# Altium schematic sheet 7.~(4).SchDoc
size 609 x 444 mm
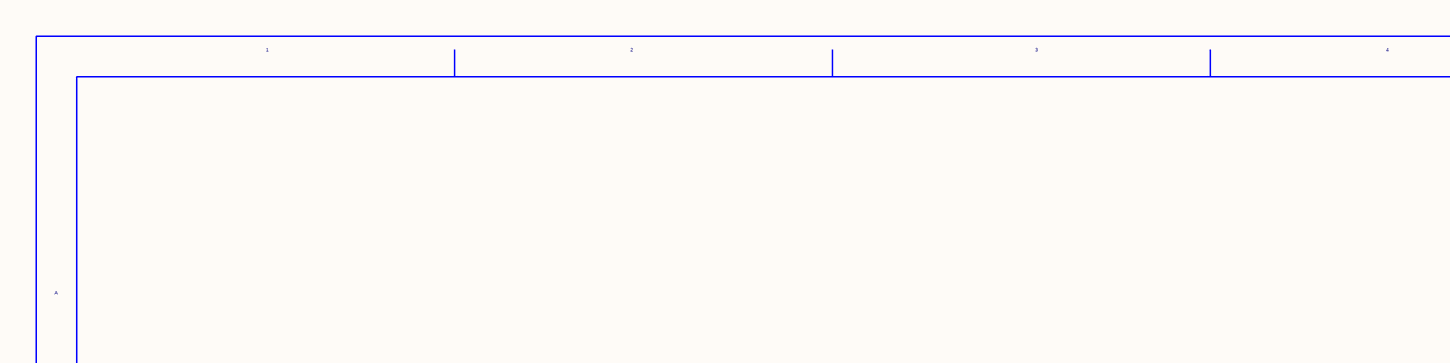
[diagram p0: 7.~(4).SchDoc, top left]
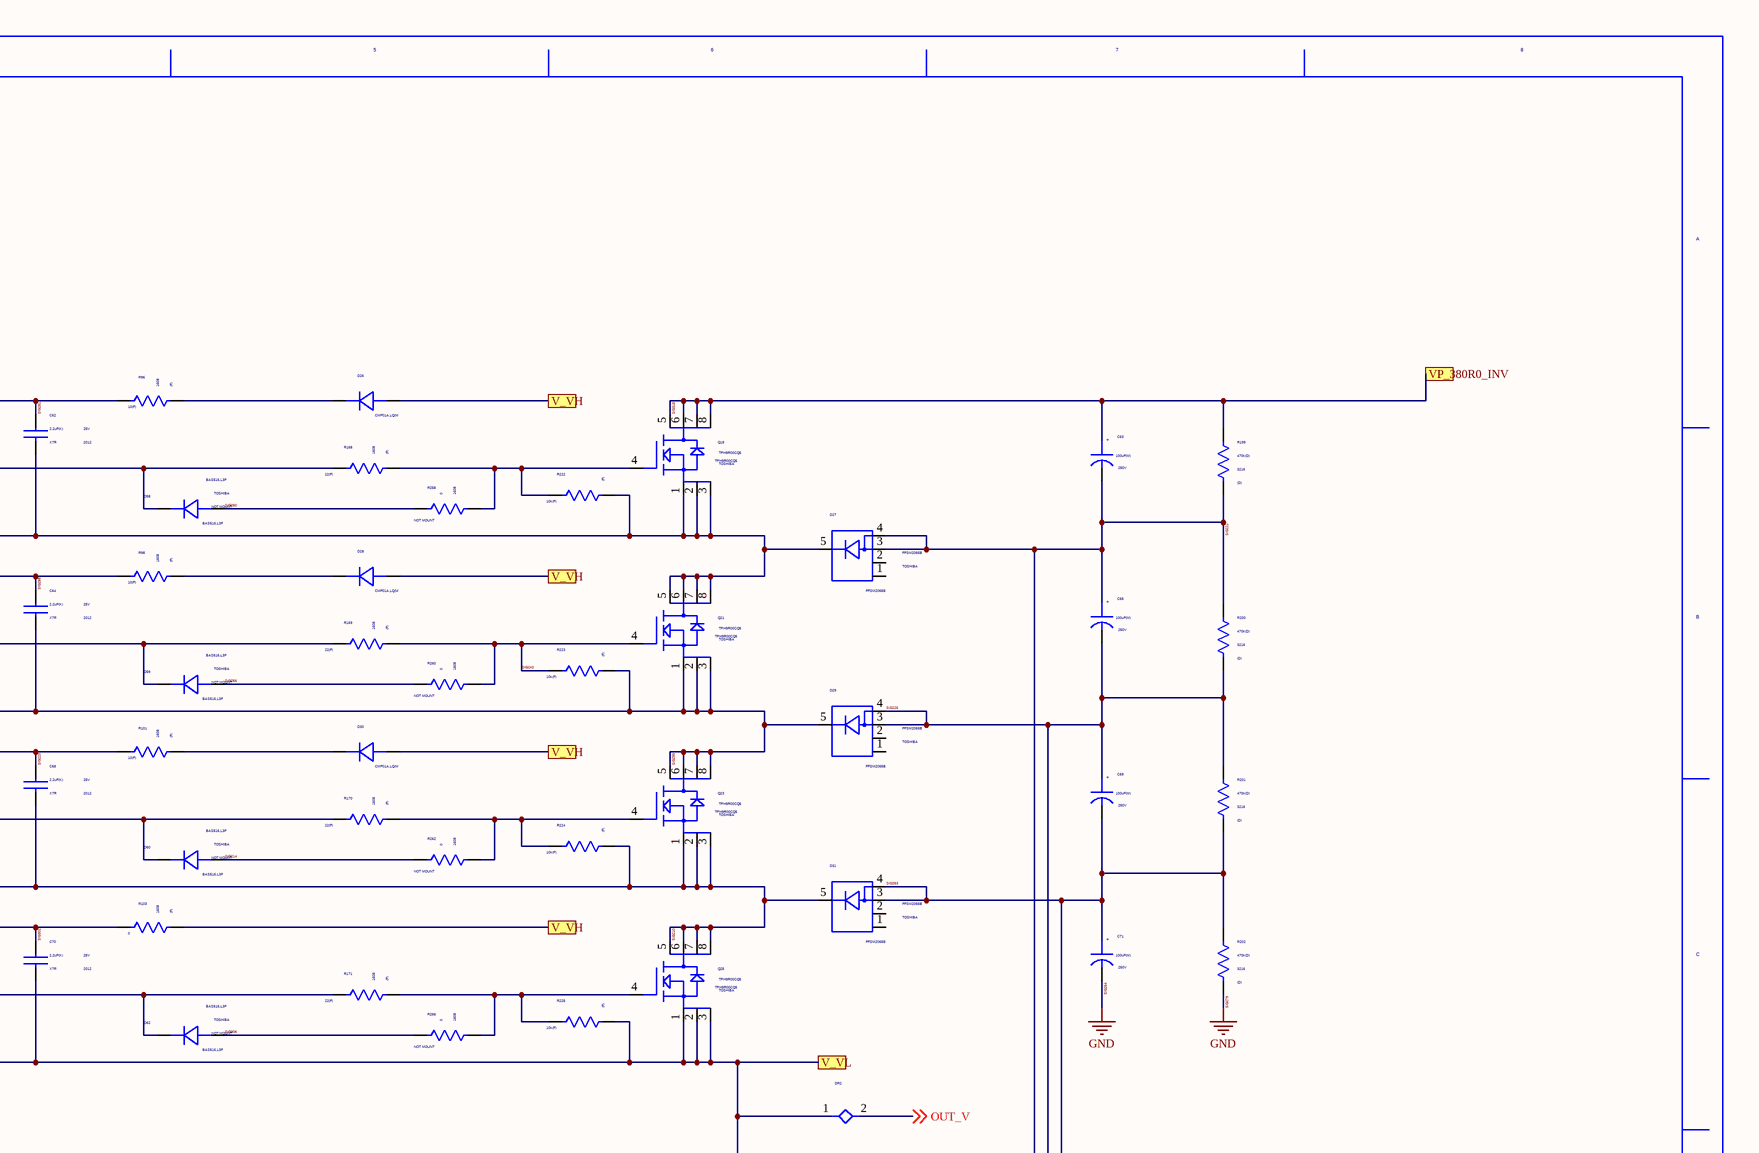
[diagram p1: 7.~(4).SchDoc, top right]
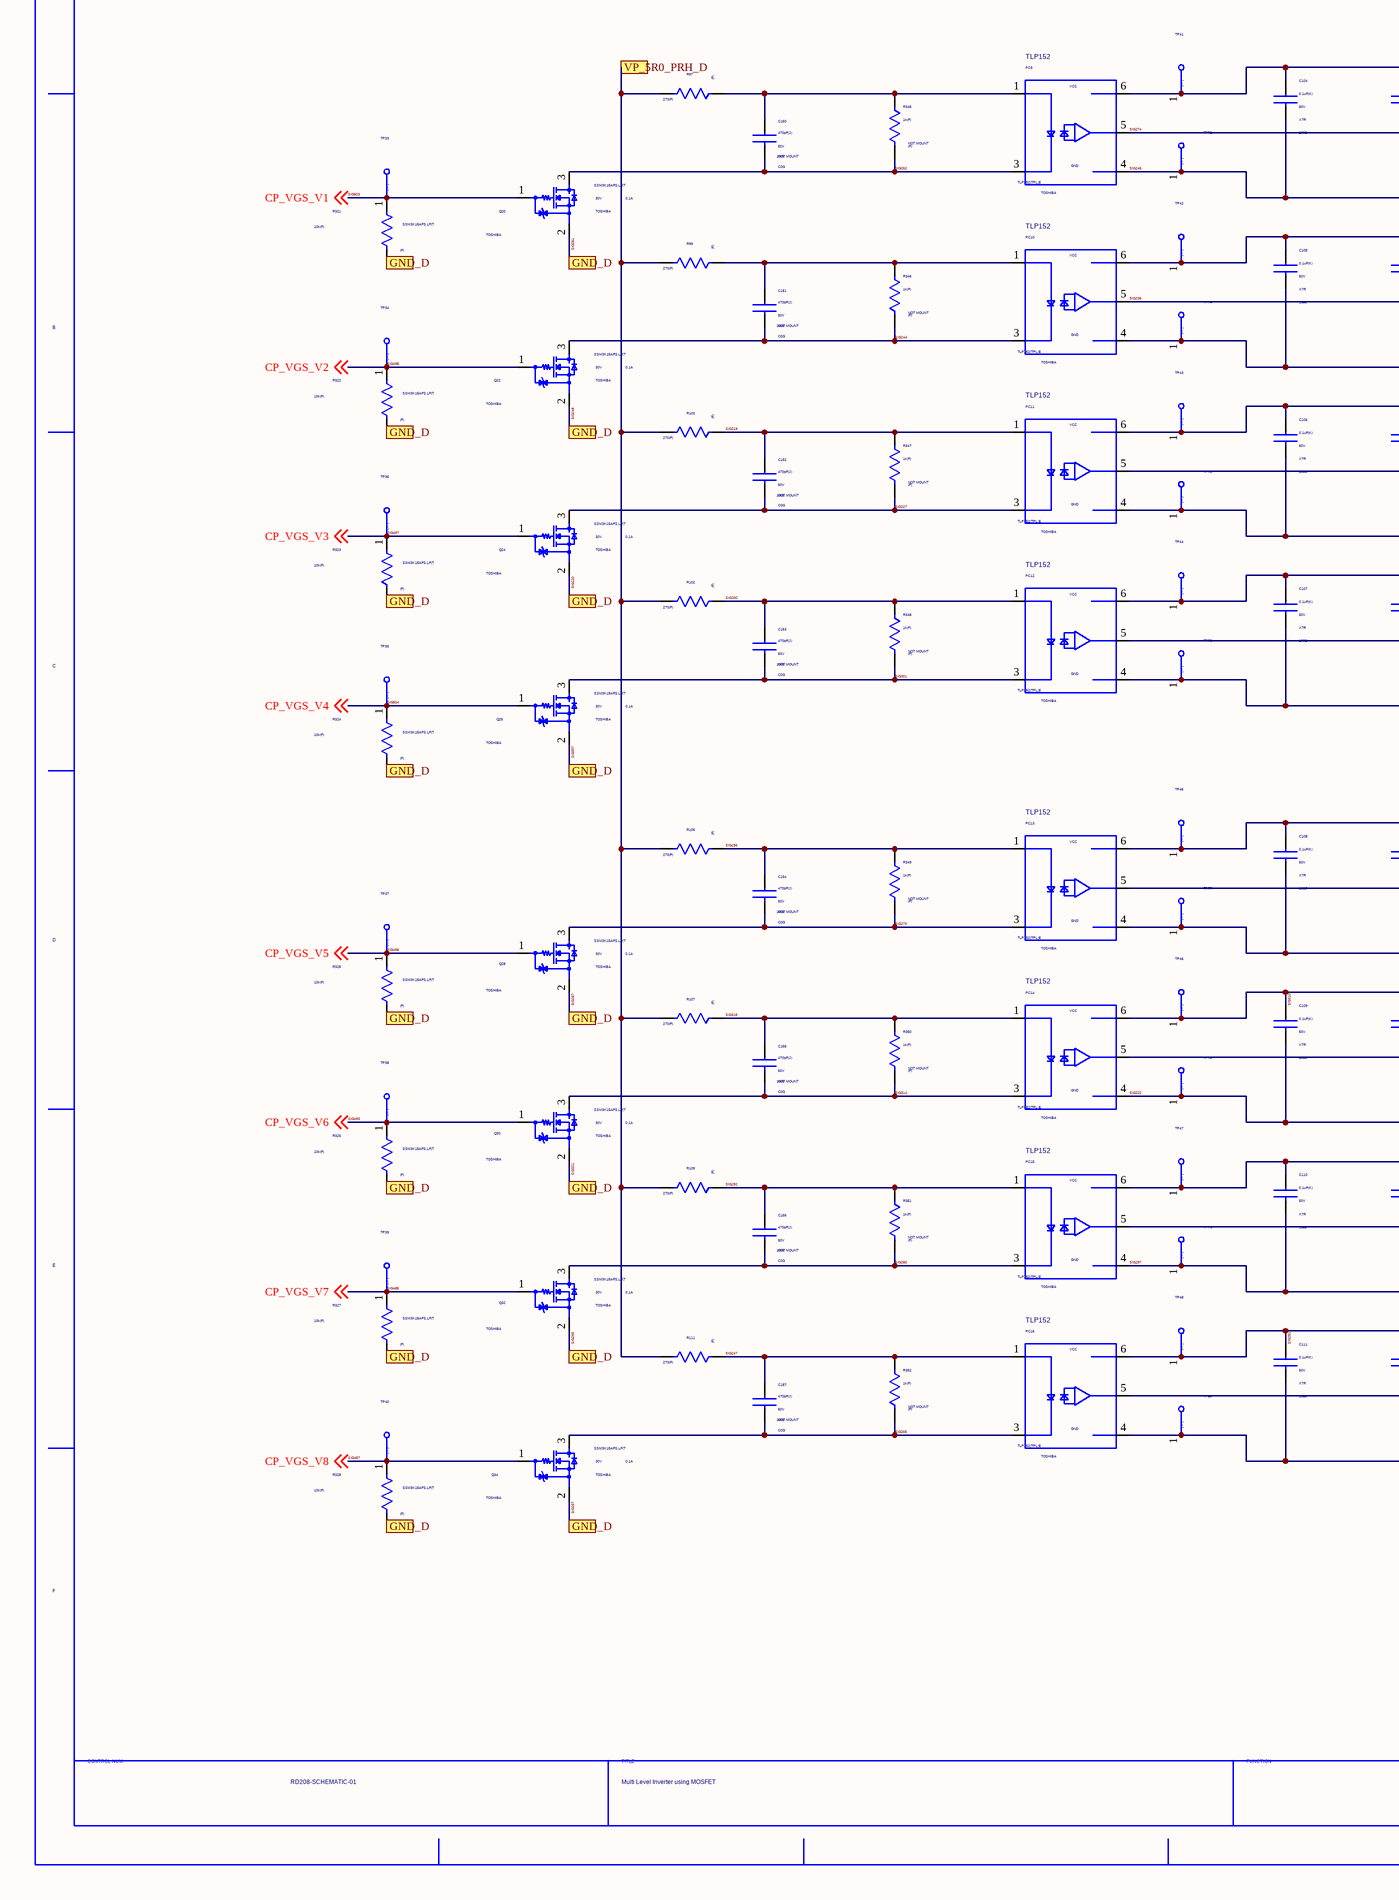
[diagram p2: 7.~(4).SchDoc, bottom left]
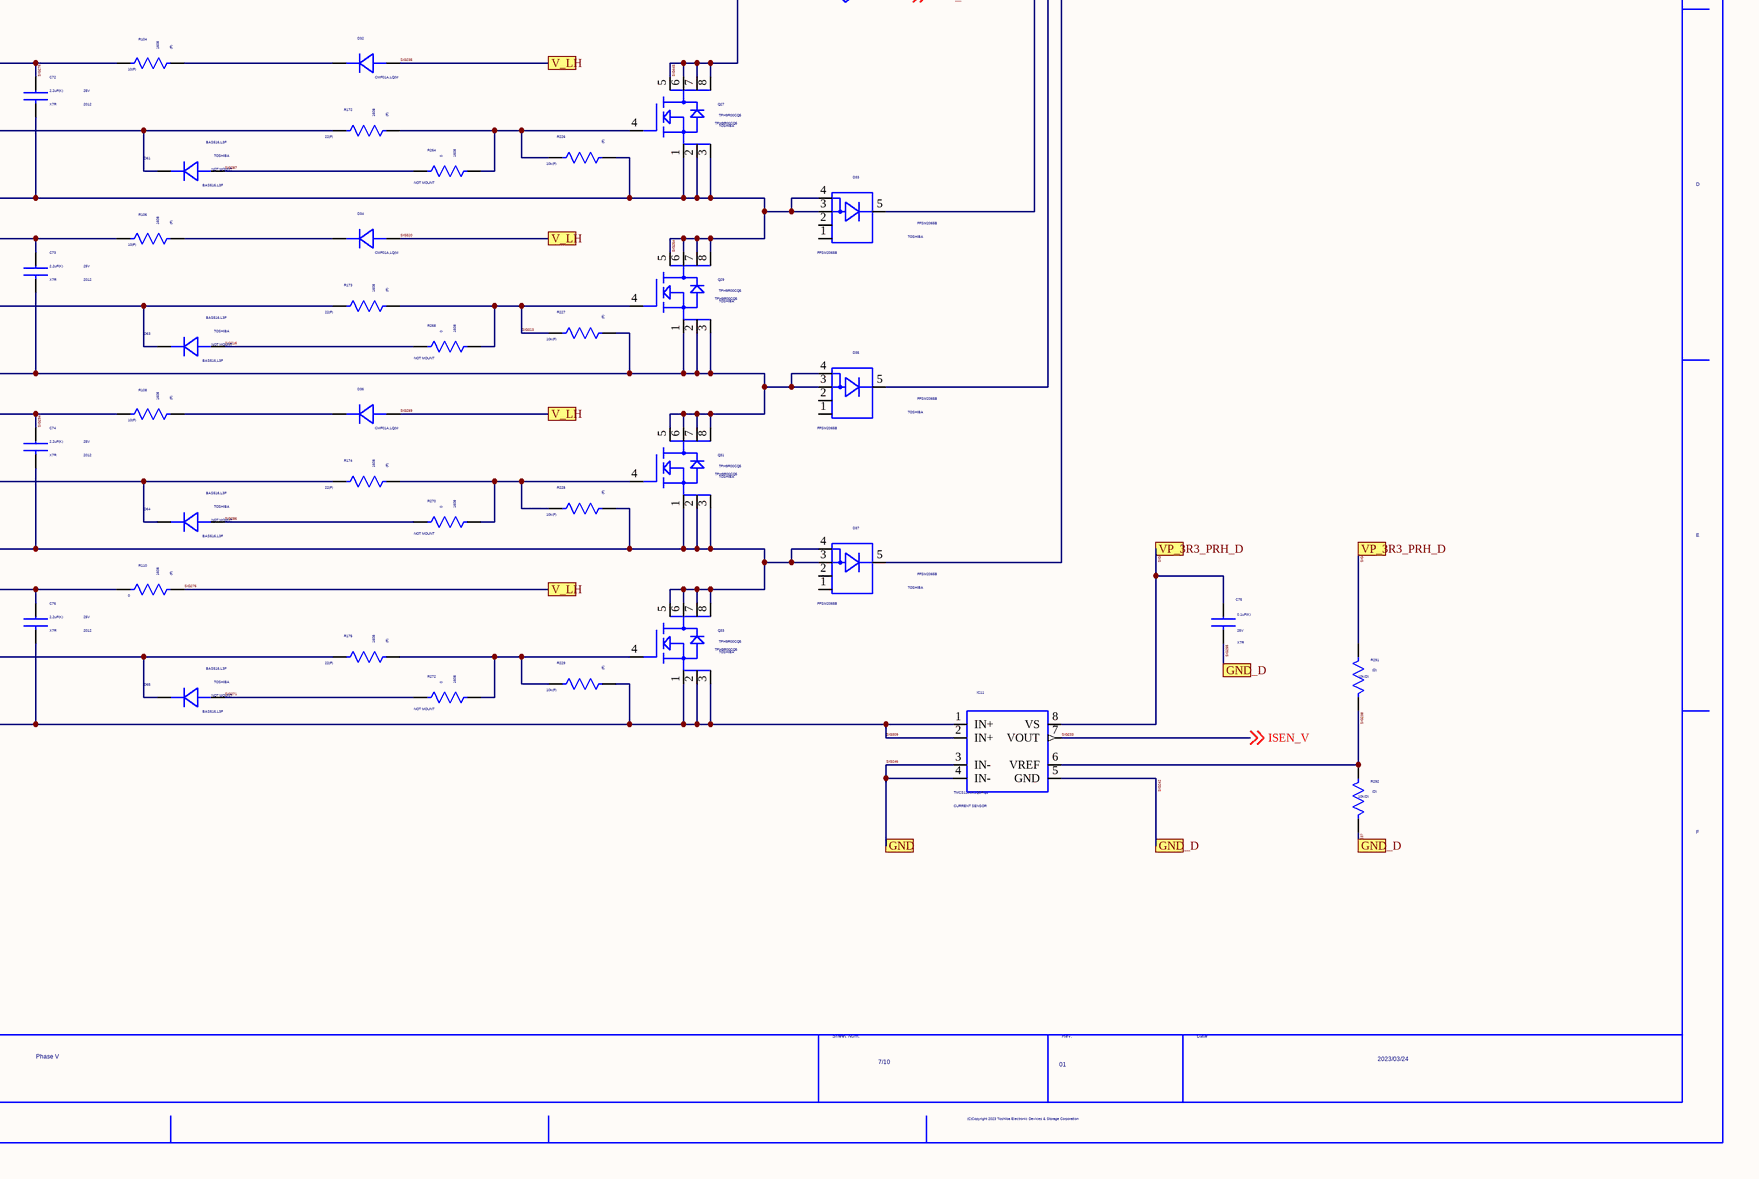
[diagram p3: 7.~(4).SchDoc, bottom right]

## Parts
C62  VAL2: 25V  SIZECODESMD: 2012  VALUE4: X7R  VAL1: 2.2uF(K)  (hidden comment: GRM21BR71E225KE11L)
C63  VAL2: 250V  VAL1: 100uF(M)  (hidden comment: EKMQ251ELL101ML25S)
C64  VAL2: 25V  SIZECODESMD: 2012  VALUE4: X7R  VAL1: 2.2uF(K)  (hidden comment: GRM21BR71E225KE11L)
C65  VAL2: 250V  VAL1: 100uF(M)  (hidden comment: EKMQ251ELL101ML25S)
C68  VAL2: 25V  SIZECODESMD: 2012  VALUE4: X7R  VAL1: 2.2uF(K)  (hidden comment: GRM21BR71E225KE11L)
C69  VAL2: 250V  VAL1: 100uF(M)  (hidden comment: EKMQ251ELL101ML25S)
C70  VAL2: 25V  SIZECODESMD: 2012  VALUE4: X7R  VAL1: 2.2uF(K)  (hidden comment: GRM21BR71E225KE11L)
C71  VAL2: 250V  VAL1: 100uF(M)  (hidden comment: EKMQ251ELL101ML25S)
C72  VAL2: 25V  SIZECODESMD: 2012  VALUE4: X7R  VAL1: 2.2uF(K)  (hidden comment: GRM21BR71E225KE11L)
C73  VAL2: 25V  SIZECODESMD: 2012  VALUE4: X7R  VAL1: 2.2uF(K)  (hidden comment: GRM21BR71E225KE11L)
C74  VAL2: 25V  SIZECODESMD: 2012  VALUE4: X7R  VAL1: 2.2uF(K)  (hidden comment: GRM21BR71E225KE11L)
C75  VAL2: 25V  VALUE4: X7R  VAL1: 0.1uF(K)  (hidden comment: GRM155R71E104KE14D)
C76  VAL2: 25V  SIZECODESMD: 2012  VALUE4: X7R  VAL1: 2.2uF(K)  (hidden comment: GRM21BR71E225KE11L)
C104  VAL2: 50V  SIZECODESMD: 1608  VALUE4: X7R  VAL1: 0.1uF(K)  (hidden comment: C1608X7R1H104K080AA)
C105  VAL2: 50V  SIZECODESMD: 1608  VALUE4: X7R  VAL1: 0.1uF(K)  (hidden comment: C1608X7R1H104K080AA)
C106  VAL2: 50V  SIZECODESMD: 1608  VALUE4: X7R  VAL1: 0.1uF(K)  (hidden comment: C1608X7R1H104K080AA)
C107  VAL2: 50V  SIZECODESMD: 1608  VALUE4: X7R  VAL1: 0.1uF(K)  (hidden comment: C1608X7R1H104K080AA)
C108  VAL2: 50V  SIZECODESMD: 1608  VALUE4: X7R  VAL1: 0.1uF(K)  (hidden comment: C1608X7R1H104K080AA)
C109  VAL2: 50V  SIZECODESMD: 1608  VALUE4: X7R  VAL1: 0.1uF(K)  (hidden comment: C1608X7R1H104K080AA)
C110  VAL2: 50V  SIZECODESMD: 1608  VALUE4: X7R  VAL1: 0.1uF(K)  (hidden comment: C1608X7R1H104K080AA)
C111  VAL2: 50V  SIZECODESMD: 1608  VALUE4: X7R  VAL1: 0.1uF(K)  (hidden comment: C1608X7R1H104K080AA)
C150  VAL2: 50V  SIZECODESMD: 1005  VALUE4: C0G  VAL1: 470pF(J)  NOTMOUNT: NOT MOUNT  (hidden comment: GRM1555C1H471JA01J)
C151  VAL2: 50V  SIZECODESMD: 1005  VALUE4: C0G  VAL1: 470pF(J)  NOTMOUNT: NOT MOUNT  (hidden comment: GRM1555C1H471JA01J)
C152  VAL2: 50V  SIZECODESMD: 1005  VALUE4: C0G  VAL1: 470pF(J)  NOTMOUNT: NOT MOUNT  (hidden comment: GRM1555C1H471JA01J)
C153  VAL2: 50V  SIZECODESMD: 1005  VALUE4: C0G  VAL1: 470pF(J)  NOTMOUNT: NOT MOUNT  (hidden comment: GRM1555C1H471JA01J)
C154  VAL2: 50V  SIZECODESMD: 1005  VALUE4: C0G  VAL1: 470pF(J)  NOTMOUNT: NOT MOUNT  (hidden comment: GRM1555C1H471JA01J)
C155  VAL2: 50V  SIZECODESMD: 1005  VALUE4: C0G  VAL1: 470pF(J)  NOTMOUNT: NOT MOUNT  (hidden comment: GRM1555C1H471JA01J)
C156  VAL2: 50V  SIZECODESMD: 1005  VALUE4: C0G  VAL1: 470pF(J)  NOTMOUNT: NOT MOUNT  (hidden comment: GRM1555C1H471JA01J)
C157  VAL2: 50V  SIZECODESMD: 1005  VALUE4: C0G  VAL1: 470pF(J)  NOTMOUNT: NOT MOUNT  (hidden comment: GRM1555C1H471JA01J)
D26  VAL1: CMF01A,LQ(M  (hidden comment: CMF01A,LQ_M)
D27  USERCOMPTEXT3: TOSHIBA  (hidden comment: FFSM2065B)
D28  VAL1: CMF01A,LQ(M  (hidden comment: CMF01A,LQ_M)
D29  USERCOMPTEXT3: TOSHIBA  (hidden comment: FFSM2065B)
D30  VAL1: CMF01A,LQ(M  (hidden comment: CMF01A,LQ_M)
D31  USERCOMPTEXT3: TOSHIBA  (hidden comment: FFSM2065B)
D32  VAL1: CMF01A,LQ(M  (hidden comment: CMF01A,LQ_M)
D33  USERCOMPTEXT3: TOSHIBA  (hidden comment: FFSM2065B)
D34  VAL1: CMF01A,LQ(M  (hidden comment: CMF01A,LQ_M)
D35  USERCOMPTEXT3: TOSHIBA  (hidden comment: FFSM2065B)
D36  VAL1: CMF01A,LQ(M  (hidden comment: CMF01A,LQ_M)
D37  USERCOMPTEXT3: TOSHIBA  (hidden comment: FFSM2065B)
D58  USERCOMPTEXT3: TOSHIBA  NOTMOUNT: NOT MOUNT  (hidden comment: BAS516,L3F)
D59  USERCOMPTEXT3: TOSHIBA  NOTMOUNT: NOT MOUNT  (hidden comment: BAS516,L3F)
D60  USERCOMPTEXT3: TOSHIBA  NOTMOUNT: NOT MOUNT  (hidden comment: BAS516,L3F)
D61  USERCOMPTEXT3: TOSHIBA  NOTMOUNT: NOT MOUNT  (hidden comment: BAS516,L3F)
D62  USERCOMPTEXT3: TOSHIBA  NOTMOUNT: NOT MOUNT  (hidden comment: BAS516,L3F)
D63  USERCOMPTEXT3: TOSHIBA  NOTMOUNT: NOT MOUNT  (hidden comment: BAS516,L3F)
D64  USERCOMPTEXT3: TOSHIBA  NOTMOUNT: NOT MOUNT  (hidden comment: BAS516,L3F)
D65  USERCOMPTEXT3: TOSHIBA  NOTMOUNT: NOT MOUNT  (hidden comment: BAS516,L3F)
DR2  STAR2  (value not drawn)
IC11  VAL2: CURRENT SENSOR  (hidden comment: TMCS1100A1QDRQ1)
PC9  SCH_NAME: TLP152  USERCOMPTEXT3: TOSHIBA  VAL3: TLP152(TPL,E  (hidden comment: TLP152_TPL,E)
PC10  SCH_NAME: TLP152  USERCOMPTEXT3: TOSHIBA  VAL3: TLP152(TPL,E  (hidden comment: TLP152_TPL,E)
PC11  SCH_NAME: TLP152  USERCOMPTEXT3: TOSHIBA  VAL3: TLP152(TPL,E  (hidden comment: TLP152_TPL,E)
PC12  SCH_NAME: TLP152  USERCOMPTEXT3: TOSHIBA  VAL3: TLP152(TPL,E  (hidden comment: TLP152_TPL,E)
PC13  SCH_NAME: TLP152  USERCOMPTEXT3: TOSHIBA  VAL3: TLP152(TPL,E  (hidden comment: TLP152_TPL,E)
PC14  SCH_NAME: TLP152  USERCOMPTEXT3: TOSHIBA  VAL3: TLP152(TPL,E  (hidden comment: TLP152_TPL,E)
PC15  SCH_NAME: TLP152  USERCOMPTEXT3: TOSHIBA  VAL3: TLP152(TPL,E  (hidden comment: TLP152_TPL,E)
PC16  SCH_NAME: TLP152  USERCOMPTEXT3: TOSHIBA  VAL3: TLP152(TPL,E  (hidden comment: TLP152_TPL,E)
Q19  USERCOMPTEXT3: TOSHIBA  (hidden comment: TPH9R00CQ5)
Q20  VAL2: 0.1A  MANUFACTURER: TOSHIBA  SIZECODESMD: 30V  VAL1: SSM3K15AFS,LF(T  (hidden comment: SSM3K15AFS,LF_T)
Q21  USERCOMPTEXT3: TOSHIBA  (hidden comment: TPH9R00CQ5)
Q22  VAL2: 0.1A  MANUFACTURER: TOSHIBA  SIZECODESMD: 30V  VAL1: SSM3K15AFS,LF(T  (hidden comment: SSM3K15AFS,LF_T)
Q23  USERCOMPTEXT3: TOSHIBA  (hidden comment: TPH9R00CQ5)
Q24  VAL2: 0.1A  MANUFACTURER: TOSHIBA  SIZECODESMD: 30V  VAL1: SSM3K15AFS,LF(T  (hidden comment: SSM3K15AFS,LF_T)
Q25  USERCOMPTEXT3: TOSHIBA  (hidden comment: TPH9R00CQ5)
Q26  VAL2: 0.1A  MANUFACTURER: TOSHIBA  SIZECODESMD: 30V  VAL1: SSM3K15AFS,LF(T  (hidden comment: SSM3K15AFS,LF_T)
Q27  USERCOMPTEXT3: TOSHIBA  (hidden comment: TPH9R00CQ5)
Q28  VAL2: 0.1A  MANUFACTURER: TOSHIBA  SIZECODESMD: 30V  VAL1: SSM3K15AFS,LF(T  (hidden comment: SSM3K15AFS,LF_T)
Q29  USERCOMPTEXT3: TOSHIBA  (hidden comment: TPH9R00CQ5)
Q30  VAL2: 0.1A  MANUFACTURER: TOSHIBA  SIZECODESMD: 30V  VAL1: SSM3K15AFS,LF(T  (hidden comment: SSM3K15AFS,LF_T)
Q31  USERCOMPTEXT3: TOSHIBA  (hidden comment: TPH9R00CQ5)
Q32  VAL2: 0.1A  MANUFACTURER: TOSHIBA  SIZECODESMD: 30V  VAL1: SSM3K15AFS,LF(T  (hidden comment: SSM3K15AFS,LF_T)
Q33  USERCOMPTEXT3: TOSHIBA  (hidden comment: TPH9R00CQ5)
Q34  VAL2: 0.1A  MANUFACTURER: TOSHIBA  SIZECODESMD: 30V  VAL1: SSM3K15AFS,LF(T  (hidden comment: SSM3K15AFS,LF_T)
R96  SIZECODESMD: 1608  VALUE4: (F)  VAL1: 10(F)  (hidden comment: ERJ3EKF10R0V)
R97  VALUE4: (F)  VAL1: 270(F)  (hidden comment: ERJ2RKF2700X)
R98  SIZECODESMD: 1608  VALUE4: (F)  VAL1: 10(F)  (hidden comment: ERJ3EKF10R0V)
R99  VALUE4: (F)  VAL1: 270(F)  (hidden comment: ERJ2RKF2700X)
R100  VALUE4: (F)  VAL1: 270(F)  (hidden comment: ERJ2RKF2700X)
R101  SIZECODESMD: 1608  VALUE4: (F)  VAL1: 10(F)  (hidden comment: ERJ3EKF10R0V)
R102  VALUE4: (F)  VAL1: 270(F)  (hidden comment: ERJ2RKF2700X)
R103  SIZECODESMD: 1608  VALUE4: (F)  VAL1: 0  (hidden comment: ERJ3EKF10R0V)
R104  SIZECODESMD: 1608  VALUE4: (F)  VAL1: 10(F)  (hidden comment: ERJ3EKF10R0V)
R105  VALUE4: (F)  VAL1: 270(F)  (hidden comment: ERJ2RKF2700X)
R106  SIZECODESMD: 1608  VALUE4: (F)  VAL1: 10(F)  (hidden comment: ERJ3EKF10R0V)
R107  VALUE4: (F)  VAL1: 270(F)  (hidden comment: ERJ2RKF2700X)
R108  SIZECODESMD: 1608  VALUE4: (F)  VAL1: 10(F)  (hidden comment: ERJ3EKF10R0V)
R109  VALUE4: (F)  VAL1: 270(F)  (hidden comment: ERJ2RKF2700X)
R110  SIZECODESMD: 1608  VALUE4: (F)  VAL1: 0  (hidden comment: ERJ3EKF10R0V)
R111  VALUE4: (F)  VAL1: 270(F)  (hidden comment: ERJ2RKF2700X)
R168  SIZECODESMD: 1608  VALUE4: (F)  VAL1: 22(F)  (hidden comment: ERJ3EKF22R0V)
R169  SIZECODESMD: 1608  VALUE4: (F)  VAL1: 22(F)  (hidden comment: ERJ3EKF22R0V)
R170  SIZECODESMD: 1608  VALUE4: (F)  VAL1: 22(F)  (hidden comment: ERJ3EKF22R0V)
R171  SIZECODESMD: 1608  VALUE4: (F)  VAL1: 22(F)  (hidden comment: ERJ3EKF22R0V)
R172  SIZECODESMD: 1608  VALUE4: (F)  VAL1: 22(F)  (hidden comment: ERJ3EKF22R0V)
R173  SIZECODESMD: 1608  VALUE4: (F)  VAL1: 22(F)  (hidden comment: ERJ3EKF22R0V)
R174  SIZECODESMD: 1608  VALUE4: (F)  VAL1: 22(F)  (hidden comment: ERJ3EKF22R0V)
R175  SIZECODESMD: 1608  VALUE4: (F)  VAL1: 22(F)  (hidden comment: ERJ3EKF22R0V)
R199  SIZECODESMD: 3216  VALUE4: (D)  VAL1: 470k(D)  (hidden comment: HV73V2BTTD4703D)
R200  SIZECODESMD: 3216  VALUE4: (D)  VAL1: 470k(D)  (hidden comment: HV73V2BTTD4703D)
R201  SIZECODESMD: 3216  VALUE4: (D)  VAL1: 470k(D)  (hidden comment: HV73V2BTTD4703D)
R202  SIZECODESMD: 3216  VALUE4: (D)  VAL1: 470k(D)  (hidden comment: HV73V2BTTD4703D)
R222  VALUE4: (F)  VAL1: 10k(F)  (hidden comment: ERJ2RKF1002X)
R223  VALUE4: (F)  VAL1: 10k(F)  (hidden comment: ERJ2RKF1002X)
R224  VALUE4: (F)  VAL1: 10k(F)  (hidden comment: ERJ2RKF1002X)
R225  VALUE4: (F)  VAL1: 10k(F)  (hidden comment: ERJ2RKF1002X)
R226  VALUE4: (F)  VAL1: 10k(F)  (hidden comment: ERJ2RKF1002X)
R227  VALUE4: (F)  VAL1: 10k(F)  (hidden comment: ERJ2RKF1002X)
R228  VALUE4: (F)  VAL1: 10k(F)  (hidden comment: ERJ2RKF1002X)
R229  VALUE4: (F)  VAL1: 10k(F)  (hidden comment: ERJ2RKF1002X)
R258  SIZECODESMD: 1608  VAL1: 0  NOTMOUNT: NOT MOUNT  (hidden comment: ERJ3GEY0R00V)
R260  SIZECODESMD: 1608  VAL1: 0  NOTMOUNT: NOT MOUNT  (hidden comment: ERJ3GEY0R00V)
R262  SIZECODESMD: 1608  VAL1: 0  NOTMOUNT: NOT MOUNT  (hidden comment: ERJ3GEY0R00V)
R264  SIZECODESMD: 1608  VAL1: 0  NOTMOUNT: NOT MOUNT  (hidden comment: ERJ3GEY0R00V)
R266  SIZECODESMD: 1608  VAL1: 0  NOTMOUNT: NOT MOUNT  (hidden comment: ERJ3GEY0R00V)
R268  SIZECODESMD: 1608  VAL1: 0  NOTMOUNT: NOT MOUNT  (hidden comment: ERJ3GEY0R00V)
R270  SIZECODESMD: 1608  VAL1: 0  NOTMOUNT: NOT MOUNT  (hidden comment: ERJ3GEY0R00V)
R272  SIZECODESMD: 1608  VAL1: 0  NOTMOUNT: NOT MOUNT  (hidden comment: ERJ3GEY0R00V)
R291  VALUE4: (D)  VAL1: 10k(D)  (hidden comment: RK73G1ETTP1002D)
R292  VALUE4: (D)  VAL1: 10k(D)  (hidden comment: RK73G1ETTP1002D)
R321  VALUE4: (F)  VAL1: 10k(F)  (hidden comment: ERJ2RKF1002X)
R322  VALUE4: (F)  VAL1: 10k(F)  (hidden comment: ERJ2RKF1002X)
R323  VALUE4: (F)  VAL1: 10k(F)  (hidden comment: ERJ2RKF1002X)
R324  VALUE4: (F)  VAL1: 10k(F)  (hidden comment: ERJ2RKF1002X)
R325  VALUE4: (F)  VAL1: 10k(F)  (hidden comment: ERJ2RKF1002X)
R326  VALUE4: (F)  VAL1: 10k(F)  (hidden comment: ERJ2RKF1002X)
R327  VALUE4: (F)  VAL1: 10k(F)  (hidden comment: ERJ2RKF1002X)
R328  VALUE4: (F)  VAL1: 10k(F)  (hidden comment: ERJ2RKF1002X)
R345  VALUE4: (F)  VAL1: 1k(F)  NOTMOUNT: NOT MOUNT  (hidden comment: ERJ2RKF1001X)
R346  VALUE4: (F)  VAL1: 1k(F)  NOTMOUNT: NOT MOUNT  (hidden comment: ERJ2RKF1001X)
R347  VALUE4: (F)  VAL1: 1k(F)  NOTMOUNT: NOT MOUNT  (hidden comment: ERJ2RKF1001X)
R348  VALUE4: (F)  VAL1: 1k(F)  NOTMOUNT: NOT MOUNT  (hidden comment: ERJ2RKF1001X)
R349  VALUE4: (F)  VAL1: 1k(F)  NOTMOUNT: NOT MOUNT  (hidden comment: ERJ2RKF1001X)
R350  VALUE4: (F)  VAL1: 1k(F)  NOTMOUNT: NOT MOUNT  (hidden comment: ERJ2RKF1001X)
R351  VALUE4: (F)  VAL1: 1k(F)  NOTMOUNT: NOT MOUNT  (hidden comment: ERJ2RKF1001X)
R352  VALUE4: (F)  VAL1: 1k(F)  NOTMOUNT: NOT MOUNT  (hidden comment: ERJ2RKF1001X)
TP33  TP  (value not drawn)
TP34  TP  (value not drawn)
TP35  TP  (value not drawn)
TP36  TP  (value not drawn)
TP37  TP  (value not drawn)
TP38  TP  (value not drawn)
TP39  TP  (value not drawn)
TP40  TP  (value not drawn)
TP41  TP  (value not drawn)
TP42  TP  (value not drawn)
TP43  TP  (value not drawn)
TP44  TP  (value not drawn)
TP45  TP  (value not drawn)
TP46  TP  (value not drawn)
TP47  TP  (value not drawn)
TP48  TP  (value not drawn)
TP73  TP  (value not drawn)
TP74  TP  (value not drawn)
TP75  TP  (value not drawn)
TP76  TP  (value not drawn)
TP77  TP  (value not drawn)
TP78  TP  (value not drawn)
TP79  TP  (value not drawn)
TP80  TP  (value not drawn)
U?  DATE: 2023/03/24  TITLE: Multi Level Inverter using MOSFET  REVISION: 01  SHEETNUMBER: 7/10  DRAWINGNUMBER: RD208-SCHEMATIC-01  FUNCTION: Phase V  (hidden comment: WAKU_DEF_A3)

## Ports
GND, GND_D, V_LH, V_VH, V_VL, VP_3R3_PRH_D, VP_5R0_PRH_D, VP_380R0_INV

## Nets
SIG264: C71.2 R202.2  [also labelled GND, SIG279]
OUT_V: DR2.2 ; off-sheet OUT_V
SIG209: D60.K(CATHODE) PC11.5 R170.1
SIG210: C68.2 C106.2 D31.5(CATHODE) PC11.4 Q23.1(S1) Q23.2(S2) Q23.3(S3) Q25.5(D1) Q25.6(D2) Q25.7(D3) Q25.8(D4) R224.2 TP75.1
SIG214: D60.A(ANODE) R262.1
SIG215: D32.K(CATHODE) R104.2
SIG216: D63.A(ANODE) R268.1
SIG219: C152.1 PC11.1 R100.2 R347.1
SIG220: C75.2 IC11.5(GND) Q20.2(E) Q22.2(E) Q24.2(E) Q26.2(E) Q28.2(E) Q30.2(E) Q32.2(E) Q34.2(E) R292.1 R321.2 R322.2 R323.2 R324.2 R325.2 R326.2 R327.2 R328.2 ; port GND_D  [also labelled SIG237, SIG242, SIG248, SIG255, SIG257, SIG261, SIG267, SIG293, SIG307, SIG321]
SIG221: C63.2 C65.1 D27.3(ANODE3) D27.4(ANODE4) D33.5(CATHODE) R199.2 R200.1
SIG222: C73.2 C109.2 D35.3(ANODE3) D35.4(ANODE4) PC14.4 Q29.1(S1) Q29.2(S2) Q29.3(S3) Q31.5(D1) Q31.6(D2) Q31.7(D3) Q31.8(D4) R227.2 TP78.1
SIG223: C68.1 C106.1 PC11.6 R101.1 TP43.1
SIG225: D61.K(CATHODE) PC13.5 R172.1
SIG226: C65.2 C69.1 D29.3(ANODE3) D29.4(ANODE4) D35.5(CATHODE) R200.2 R201.1
SIG227: C152.2 PC11.3 Q24.3(C) R347.2
SIG230: D28.K(CATHODE) R98.2
SIG231: D64.K(CATHODE) PC15.5 R174.1
SIG232: D34.K(CATHODE) R106.2
SIG233: IC11.7(VOUT) ; off-sheet ISEN_V  [also labelled ISEN_V]
SIG235: D32.A(ANODE) D34.A(ANODE) D36.A(ANODE) R110.2 ; port V_LH  [also labelled SIG275, SIG289, SIG320]
SIG236: D59.K(CATHODE) PC10.5 R169.1
SIG238: IC11.6(VREF) R291.1 R292.2
SIG239: C75.1 IC11.8(VS) R291.2 ; port VP_3R3_PRH_D  [also labelled SIG241]
SIG243: Q21.4(G) R169.2 R223.1 R260.2
SIG244: C151.2 PC10.3 Q22.3(C) R346.2
SIG245: C62.2 C104.2 D27.5(CATHODE) PC9.4 Q19.1(S1) Q19.2(S2) Q19.3(S3) Q21.5(D1) Q21.6(D2) Q21.7(D3) Q21.8(D4) R222.2 TP73.1
SIG246: IC11.3(IN-) IC11.4(IN-) ; port GND
SIG247: C157.1 PC16.1 R111.2 R352.1
SIG252: D36.K(CATHODE) R108.2
SIG253: C69.2 C71.1 D31.3(ANODE3) D31.4(ANODE4) D37.5(CATHODE) R201.2 R202.1
SIG254: C72.2 C108.2 D33.3(ANODE3) D33.4(ANODE4) PC13.4 Q27.1(S1) Q27.2(S2) Q27.3(S3) Q29.5(D1) Q29.6(D2) Q29.7(D3) Q29.8(D4) R226.2 TP77.1
SIG256: Q27.4(G) R172.2 R226.1 R264.2
SIG258: C64.1 C105.1 PC10.6 R98.1 TP42.1
SIG260: D58.A(ANODE) R258.1
SIG262: C150.2 PC9.3 Q20.3(C) R345.2
SIG263: Q33.4(G) R175.2 R229.1 R272.2
SIG265: C157.2 PC16.3 Q34.3(C) R352.2
SIG266: D59.A(ANODE) R260.1
SIG269: C151.1 PC10.1 R99.2 R346.1
SIG270: C154.2 PC13.3 Q28.3(C) R349.2
SIG271: D65.A(ANODE) R272.1
SIG272: D65.K(CATHODE) PC16.5 R175.1
SIG274: D58.K(CATHODE) PC9.5 R168.1
SIG276: C150.1 PC9.1 R97.2 R345.1
SIG278: C72.1 C108.1 PC13.6 R104.1 TP45.1
SIG280: C156.2 PC15.3 Q32.3(C) R351.2
SIG281: C62.1 C104.1 PC9.6 R96.1 TP41.1
SIG282: Q19.4(G) R168.2 R222.1 R258.2
SIG285: D26.K(CATHODE) R96.2
SIG286: D64.A(ANODE) R270.1
SIG287: D61.A(ANODE) R264.1
SIG291: C76.1 C111.1 PC16.6 R110.1 TP48.1
SIG292: C156.1 PC15.1 R109.2 R351.1
SIG294: C74.1 C110.1 PC15.6 R108.1 TP47.1
SIG295: Q31.4(G) R174.2 R228.1 R270.2
SIG296: C154.1 PC13.1 R105.2 R349.1
SIG297: C74.2 C110.2 D37.3(ANODE3) D37.4(ANODE4) PC15.4 Q31.1(S1) Q31.2(S2) Q31.3(S3) Q33.5(D1) Q33.6(D2) Q33.7(D3) Q33.8(D4) R228.2 TP79.1
SIG298: D30.K(CATHODE) R101.2
SIG299: C64.2 C105.2 D29.5(CATHODE) PC10.4 Q21.1(S1) Q21.2(S2) Q21.3(S3) Q23.5(D1) Q23.6(D2) Q23.7(D3) Q23.8(D4) R223.2 TP74.1
SIG300: C153.1 PC12.1 R102.2 R348.1
SIG301: C153.2 PC12.3 Q26.3(C) R348.2
SIG302: C70.1 C107.1 PC12.6 R103.1 TP44.1
SIG305: Q25.4(G) R171.2 R225.1 R266.2
SIG306: D62.A(ANODE) R266.1
SIG309: C76.2 C111.2 IC11.1(IN+) IC11.2(IN+) PC16.4 Q33.1(S1) Q33.2(S2) Q33.3(S3) R229.2 TP80.1
SIG310: C73.1 C109.1 PC14.6 R106.1 TP46.1
SIG313: Q29.4(G) R173.2 R227.1 R268.2
SIG314: C155.2 PC14.3 Q30.3(C) R350.2
SIG315: C155.1 PC14.1 R107.2 R350.1
SIG316: D62.K(CATHODE) PC12.5 R171.1
SIG317: Q23.4(G) R170.2 R224.1 R262.2
SIG318: C63.1 Q19.5(D1) Q19.6(D2) Q19.7(D3) Q19.8(D4) R199.1 ; port VP_380R0_INV
SIG319: D63.K(CATHODE) PC14.5 R173.1
SIG445: C70.2 C107.2 DR2.1 PC12.4 Q25.1(S1) Q25.2(S2) Q25.3(S3) Q27.5(D1) Q27.6(D2) Q27.7(D3) Q27.8(D4) R225.2 TP76.1 ; port V_VL
SIG485: Q32.1(B) R327.1 TP39.1 ; off-sheet CP_VGS_V7  [also labelled CP_VGS_V7]
SIG487: Q34.1(B) R328.1 TP40.1 ; off-sheet CP_VGS_V8  [also labelled CP_VGS_V8]
SIG493: Q30.1(B) R326.1 TP38.1 ; off-sheet CP_VGS_V6  [also labelled CP_VGS_V6]
SIG495: Q22.1(B) R322.1 TP34.1 ; off-sheet CP_VGS_V2  [also labelled CP_VGS_V2]
SIG497: Q24.1(B) R323.1 TP35.1 ; off-sheet CP_VGS_V3  [also labelled CP_VGS_V3]
SIG498: Q28.1(B) R325.1 TP37.1 ; off-sheet CP_VGS_V5  [also labelled CP_VGS_V5]
SIG503: Q20.1(B) R321.1 TP33.1 ; off-sheet CP_VGS_V1  [also labelled CP_VGS_V1]
SIG504: Q26.1(B) R324.1 TP36.1 ; off-sheet CP_VGS_V4  [also labelled CP_VGS_V4]
V_VH: D26.A(ANODE) D28.A(ANODE) D30.A(ANODE) R103.2 ; port V_VH
VP_5R0_PRH_D: R97.1 R99.1 R100.1 R102.1 R105.1 R107.1 R109.1 R111.1 ; port VP_5R0_PRH_D

Not connected (* = marked no-connect by the designer): D27 1(NC1) 2(NC2); D29 1(NC1) 2(NC2); D31 1(NC1) 2(NC2); D33 1(NC1) 2(NC2); D35 1(NC1) 2(NC2); D37 1(NC1) 2(NC2)

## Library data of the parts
C62 C64 C68 C70 C72-C74 C76 = GRM21BR71E225KE11L: MANUFACTURER: MURATA; ITEM: CAP Ceramic; TIME: 08:44:45; UPDATEUSER: t5459927; SAVECOUNT: 1; OriginalSymbolOrigin: (0,0); INSTANCENAME: INS15860000
C63 = EKMQ251ELL101ML25S: MANUFACTURER: Nippon Chemi-Con; ITEM: CAP ALUM; TIME: 08:44:45; UPDATEUSER: t5459927; SAVECOUNT: 1; OriginalSymbolOrigin: (0,2540); INSTANCENAME: INS16070082
C65 = EKMQ251ELL101ML25S: MANUFACTURER: Nippon Chemi-Con; ITEM: CAP ALUM; TIME: 08:44:45; UPDATEUSER: t5459927; SAVECOUNT: 1; OriginalSymbolOrigin: (0,2540); INSTANCENAME: INS16070102
C69 = EKMQ251ELL101ML25S: MANUFACTURER: Nippon Chemi-Con; ITEM: CAP ALUM; TIME: 08:44:45; UPDATEUSER: t5459927; SAVECOUNT: 1; OriginalSymbolOrigin: (0,2540); INSTANCENAME: INS16070122
C71 = EKMQ251ELL101ML25S: MANUFACTURER: Nippon Chemi-Con; ITEM: CAP ALUM; TIME: 08:44:45; UPDATEUSER: t5459927; SAVECOUNT: 1; OriginalSymbolOrigin: (0,2540); INSTANCENAME: INS16070142
C75 = GRM155R71E104KE14D: MANUFACTURER: MURATA; ITEM: CAP Ceramic; SIZECODESMD: 1005; TIME: 08:44:45; UPDATEUSER: t5459927; SAVECOUNT: 1; OriginalSymbolOrigin: (0,0); INSTANCENAME: INS16776295
C104-C111 = C1608X7R1H104K080AA: MANUFACTURER: TDK; ITEM: CAP Ceramic; TIME: 08:44:45; UPDATEUSER: t5459927; SAVECOUNT: 1; OriginalSymbolOrigin: (0,0); INSTANCENAME: INS16097035
C150-C157 = GRM1555C1H471JA01J: MANUFACTURER: MURATA; ITEM: CAP Ceramic; TIME: 08:44:46; UPDATEUSER: t5459927; SAVECOUNT: 1; OriginalSymbolOrigin: (0,0); INSTANCENAME: INS17224098
D26 D28 D30 D32 D34 D36 = CMF01A,LQ_M: MANUFACTURER: TOSHIBA; COMP: CMF01A_LQ_M; ITEM: DIODE; TIME: 08:44:46; UPDATEUSER: t5459927; SAVECOUNT: 1; OriginalSymbolOrigin: (0,0); INSTANCENAME: INS15860772
D27 D29 D31 D33 D35 D37 = FFSM2065B: MANUFACTURER: ON_SEMI; ITEM: DIODE; TIME: 08:44:45; UPDATEUSER: t5459927; SAVECOUNT: 1; SAVEAREA0: -3235,-11101,10576,-990; OriginalSymbolOrigin: (0,0); INSTANCENAME: INS16711377
D58-D65 = BAS516,L3F: COMP: BAS516_L3F; ITEM: DIODE; TIME: 08:44:45; UPDATEUSER: t5459927; SAVECOUNT: 1; OriginalSymbolOrigin: (0,0); INSTANCENAME: INS16674713
DR2 = STAR2: TIME: 12:37:47; UPDATEUSER: d5009410; UPDATETIME: 12:51:51; SAVECOUNT: 17; SAVEAREA0: -6564,-5245,9999,5672; OriginalSymbolOrigin: (-2540,2540); COMP: ONEPOINT
IC11 = TMCS1100A1QDRQ1: MANUFACTURER: TI; ITEM: IC CurrentSensor; TIME: 08:44:45; UPDATEUSER: PS4_common_PC; UPDATETIME: 16:01:14; SAVECOUNT: 3; SAVEAREA0: -10605,-15555,25377,840; OriginalSymbolOrigin: (0,0)
PC9-PC16 = TLP152_TPL,E: ITEM: Photocoupler; COMP: TLP152_TPL_E; TIME: 08:44:45; UPDATEUSER: t5459927; SAVECOUNT: 1; OriginalSymbolOrigin: (0,0); INSTANCENAME: INS15861608
Q19 Q21 Q23 Q25 Q27 Q29 Q31 Q33 = TPH9R00CQ5: ITEM: FET; ORDER: 0; TIME: 08:44:45; UPDATEUSER: t5459927; SAVECOUNT: 1; OriginalSymbolOrigin: (0,0); INSTANCENAME: INS15860992
Q20 Q22 Q24 Q26 Q28 Q30 Q32 Q34 = SSM3K15AFS,LF_T: ITEM: Digital Transistor NPN; COMP: SSM3K15AFS-123; ORDER: 0; TIME: 08:44:45; UPDATEUSER: t5459927; SAVECOUNT: 1; OriginalSymbolOrigin: (0,0); INSTANCENAME: INS15859756
R96 R98 R101 R104 R106 R108 = ERJ3EKF10R0V: MANUFACTURER: Panasonic; ITEM: Register; VAL2: 100mW; TIME: 08:44:45; UPDATEUSER: t5459927; SAVECOUNT: 1; OriginalSymbolOrigin: (0,0); INSTANCENAME: INS16646496
R97 R99 R100 R102 R105 R107 R109 R111 = ERJ2RKF2700X: MANUFACTURER: Panasonic; ITEM: Register; VAL2: 100mW; SIZECODESMD: 1005; TIME: 08:44:45; UPDATEUSER: t5459927; SAVECOUNT: 1; OriginalSymbolOrigin: (0,0); INSTANCENAME: INS16151457
R103 R110 = ERJ3EKF10R0V: MANUFACTURER: Panasonic; ITEM: Register; VAL2: 1/10W; COMP: ERJ3GEY0R00V; TIME: 08:44:45; UPDATEUSER: t5459927; SAVECOUNT: 1; OriginalSymbolOrigin: (0,0); INSTANCENAME: INS16646496
R168-R175 = ERJ3EKF22R0V: MANUFACTURER: Panasonic; ITEM: Register; VAL2: 100mW; TIME: 08:44:45; UPDATEUSER: t5459927; SAVECOUNT: 1; OriginalSymbolOrigin: (0,0); INSTANCENAME: INS17210794
R199 = HV73V2BTTD4703D: MANUFACTURER: KOA; ITEM: Register; VAL2: 0.33W; TIME: 08:44:45; UPDATEUSER: t5459927; SAVECOUNT: 1; OriginalSymbolOrigin: (0,0); INSTANCENAME: INS16806843
R200 = HV73V2BTTD4703D: MANUFACTURER: KOA; ITEM: Register; VAL2: 0.33W; TIME: 08:44:45; UPDATEUSER: t5459927; SAVECOUNT: 1; OriginalSymbolOrigin: (0,0); INSTANCENAME: INS16806859
R201 = HV73V2BTTD4703D: MANUFACTURER: KOA; ITEM: Register; VAL2: 0.33W; TIME: 08:44:45; UPDATEUSER: t5459927; SAVECOUNT: 1; OriginalSymbolOrigin: (0,0); INSTANCENAME: INS16806875
R202 = HV73V2BTTD4703D: MANUFACTURER: KOA; ITEM: Register; VAL2: 0.33W; TIME: 08:44:45; UPDATEUSER: t5459927; SAVECOUNT: 1; OriginalSymbolOrigin: (0,0); INSTANCENAME: INS16806891
R222-R229 = ERJ2RKF1002X: MANUFACTURER: Panasonic; ITEM: Register; VAL2: 100mW; SIZECODESMD: 1005; TIME: 08:44:45; UPDATEUSER: t5459927; SAVECOUNT: 1; OriginalSymbolOrigin: (0,0); INSTANCENAME: INS16648754
R258 R260 R262 R264 R266 R268 R270 R272 = ERJ3GEY0R00V: MANUFACTURER: Panasonic; ITEM: Register; VAL2: 1/10W; TIME: 08:44:45; UPDATEUSER: t5459927; SAVECOUNT: 1; OriginalSymbolOrigin: (0,0); INSTANCENAME: INS16674743
R291 = RK73G1ETTP1002D: MANUFACTURER: KOA; ITEM: Register; VAL2: 100mW; SIZECODESMD: 1005; TIME: 08:44:46; UPDATEUSER: t5459927; SAVECOUNT: 1; OriginalSymbolOrigin: (0,0); INSTANCENAME: INS16808670
R292 = RK73G1ETTP1002D: MANUFACTURER: KOA; ITEM: Register; VAL2: 100mW; SIZECODESMD: 1005; TIME: 08:44:46; UPDATEUSER: t5459927; SAVECOUNT: 1; OriginalSymbolOrigin: (0,0); INSTANCENAME: INS16808683
R321-R328 = ERJ2RKF1002X: MANUFACTURER: Panasonic; ITEM: Register; VAL2: 100mW; SIZECODESMD: 1005; TIME: 08:44:45; UPDATEUSER: t5459927; SAVECOUNT: 1; OriginalSymbolOrigin: (0,0); INSTANCENAME: INS17222356
R345-R352 = ERJ2RKF1001X: MANUFACTURER: Panasonic; ITEM: Register; VAL2: 100mW; SIZECODESMD: 1005; TIME: 08:44:45; UPDATEUSER: t5459927; SAVECOUNT: 1; OriginalSymbolOrigin: (0,0); INSTANCENAME: INS17224061
TP33-TP48 TP73-TP80 = TP: TIME: 16:12:21; UPDATEUSER: fukuda-y; UPDATETIME: 16:18:11; SAVECOUNT: 2; SAVEAREA0: -242,-92,12810,7836; OriginalSymbolOrigin: (0,7620); VAL3: TH Hole dia. 1.0; COMP: TP-TH1.0-L1.6
U? = WAKU_DEF_A3: PLOTTIME: HH:MM; SAVEAREA0: -311037,-554865,914355,115662; TIME: 14:30:25; UPDATEUSER: PS4_common_PC; UPDATETIME: 08:25:30; SAVECOUNT: 18; ZONEOFFSETX: 36; ZONEOFFSETY: -24; OriginalSymbolOrigin: (12700,-12700)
